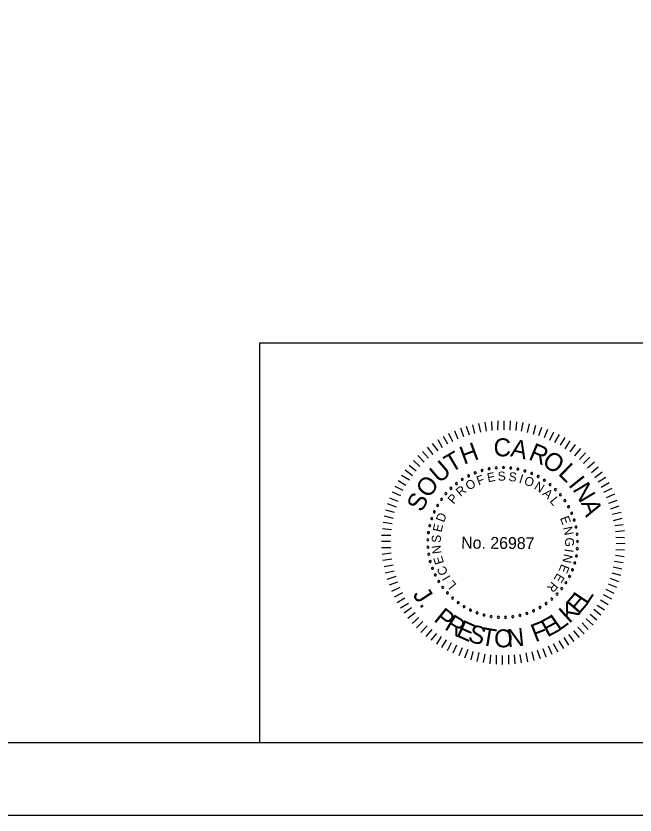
# Model space of a CAD drawing. Extents: x -125.5 to -89.4, y -5.1 to 16.9.
# Drawn here: x -104.58 to -100.31, y -5.07 to 0.43 of the extents above; entities that cross this region are included whole.
import ezdxf

# ---------------------------------------------------------------- set-up
doc = ezdxf.new("R2010")
doc.units = 0
for name, color, linetype in [('BR_BORDER LINES', 7, 'Continuous'), ('BR_TEXT', 7, 'Continuous'), ('Level 31', 7, 'Continuous')]:
    doc.layers.add(name, color=color, linetype=linetype)

msp = doc.modelspace()

# ---------------------------------------------------------------- linework, layer by layer
at = {"layer": 'BR_BORDER LINES'}
for p, q in [((-102.8989, -1.8161), (-97.5337, -1.8161)), ((-102.8989, -4.5661), (-102.8989, -1.8161)), ((-123.6994, -4.5662), (-90.0334, -4.5662))]:
    msp.add_line(p, q, dxfattribs=at)
at = {"layer": 'BR_TEXT'}
for p, q in [((-101.3372, -2.423), (-101.3461, -2.362)), ((-101.2977, -2.419), (-101.3015, -2.3581)), ((-101.2582, -2.4168), (-101.2576, -2.3524)), ((-101.2161, -2.4146), (-101.2156, -2.3528)), ((-101.1741, -2.4175), (-101.1718, -2.3531)), ((-101.1338, -2.4204), (-101.129, -2.3595)), ((-101.0952, -2.425), (-101.0844, -2.3642)), ((-101.4937, -2.4629), (-101.5147, -2.4044)), ((-101.4541, -2.4504), (-101.476, -2.3927)), ((-101.418, -2.4404), (-101.4312, -2.3793)), ((-101.3767, -2.4304), (-101.3908, -2.3711)), ((-101.0549, -2.4331), (-101.0407, -2.374)), ((-101.0138, -2.4437), (-100.9979, -2.3829)), ((-100.977, -2.4543), (-100.9551, -2.397)), ((-100.9376, -2.4675), (-100.9157, -2.4093)), ((-101.604, -2.5144), (-101.6344, -2.46)), ((-101.5695, -2.4966), (-101.5957, -2.4406)), ((-101.5325, -2.4798), (-101.556, -2.4238)), ((-100.9017, -2.485), (-100.8738, -2.4294)), ((-100.8658, -2.5024), (-100.8345, -2.4469)), ((-100.8282, -2.5208), (-100.796, -2.467)), ((-101.6704, -2.5593), (-101.7095, -2.5083)), ((-101.6394, -2.5381), (-101.6698, -2.4838)), ((-100.795, -2.5451), (-100.761, -2.4913)), ((-100.7617, -2.5668), (-100.7252, -2.5165)), ((-101.7369, -2.6094), (-101.7786, -2.5644)), ((-101.7041, -2.5847), (-101.744, -2.5346)), ((-100.7293, -2.5928), (-100.6886, -2.5434)), ((-100.6977, -2.618), (-100.6545, -2.5737)), ((-101.7958, -2.6673), (-101.8392, -2.6248)), ((-101.7663, -2.6366), (-101.8106, -2.5925)), ((-100.6697, -2.6456), (-100.6264, -2.6022)), ((-100.6416, -2.6768), (-100.594, -2.6351)), ((-101.8469, -2.732), (-101.8964, -2.6922)), ((-101.8209, -2.6988), (-101.8704, -2.6598)), ((-100.6144, -2.7088), (-100.5677, -2.6705)), ((-101.8686, -2.761), (-101.9224, -2.728)), ((-100.5906, -2.7424), (-100.5414, -2.7033)), ((-100.5686, -2.7718), (-100.516, -2.7396)), ((-101.9104, -2.8319), (-101.9668, -2.804)), ((-101.893, -2.7977), (-101.9467, -2.7656)), ((-100.5466, -2.8089), (-100.4931, -2.7776)), ((-101.9279, -2.8687), (-101.9852, -2.8433)), ((-100.5288, -2.8433), (-100.4711, -2.8164)), ((-100.5111, -2.8804), (-100.4543, -2.856)), ((-101.9454, -2.9072), (-102.0035, -2.8852)), ((-100.4943, -2.9192), (-100.4374, -2.8982)), ((-101.97, -2.9833), (-102.0308, -2.9682)), ((-101.9577, -2.9474), (-102.0193, -2.9246)), ((-100.4809, -2.9596), (-100.4232, -2.9378)), ((-101.9772, -3.0253), (-102.0397, -3.0094)), ((-100.4708, -2.9957), (-100.4107, -2.9816)), ((-100.4626, -3.0378), (-100.4024, -3.0229)), ((-101.9878, -3.0613), (-102.0487, -3.0531)), ((-100.4543, -3.074), (-100.3951, -3.0667)), ((-101.9925, -3.1024), (-102.0542, -3.0951)), ((-100.4478, -3.1152), (-100.3868, -3.1088)), ((-101.9974, -3.183), (-102.06, -3.1825)), ((-101.9954, -3.1419), (-102.0597, -3.1414)), ((-100.4464, -3.1547), (-100.3863, -3.1552)), ((-101.9961, -3.226), (-102.0604, -3.2272)), ((-100.4471, -3.2388), (-100.3871, -3.241)), ((-100.4442, -3.1959), (-100.3833, -3.1964)), ((-101.9938, -3.2646), (-102.0556, -3.2718)), ((-100.4492, -3.2774), (-100.3883, -3.2856)), ((-101.9898, -3.3058), (-102.0509, -3.3148)), ((-101.9799, -3.3454), (-102.0426, -3.3586)), ((-100.4564, -3.3185), (-100.3972, -3.3284)), ((-101.9733, -3.3875), (-102.0344, -3.4016)), ((-100.4742, -3.3999), (-100.4143, -3.415)), ((-100.4653, -3.3579), (-100.4053, -3.3721)), ((-101.9616, -3.4245), (-102.0236, -3.4454)), ((-101.95, -3.4632), (-102.0085, -3.4842)), ((-100.4848, -3.4367), (-100.4275, -3.4586)), ((-101.9331, -3.5003), (-101.9908, -3.5272)), ((-100.5163, -3.512), (-100.4599, -3.5399)), ((-100.4989, -3.4752), (-100.4424, -3.4971)), ((-101.9162, -3.5364), (-101.9731, -3.566)), ((-101.8994, -3.5735), (-101.9537, -3.6048)), ((-100.5346, -3.5479), (-100.4774, -3.5784)), ((-101.8756, -3.6106), (-101.93, -3.6419)), ((-100.5756, -3.6213), (-100.5235, -3.6535)), ((-100.553, -3.5846), (-100.5, -3.6168)), ((-101.8544, -3.6399), (-101.9045, -3.6764)), ((-101.829, -3.6736), (-101.8791, -3.7127)), ((-100.6224, -3.6836), (-100.5764, -3.7234)), ((-100.5981, -3.6503), (-100.5495, -3.6876)), ((-101.8043, -3.7073), (-101.8485, -3.7481)), ((-101.7754, -3.7333), (-101.8204, -3.7784)), ((-100.6502, -3.7168), (-100.6033, -3.7584)), ((-101.7465, -3.7636), (-101.7889, -3.8095)), ((-101.714, -3.7895), (-101.7548, -3.8364)), ((-100.7073, -3.7721), (-100.6648, -3.8188)), ((-100.6787, -3.7423), (-100.6362, -3.7882)), ((-101.6808, -3.8156), (-101.7207, -3.8633)), ((-101.6501, -3.8373), (-101.6814, -3.8894)), ((-100.8057, -3.8443), (-100.7727, -3.8969)), ((-100.772, -3.8231), (-100.7364, -3.8714)), ((-100.7392, -3.7976), (-100.6993, -3.8452)), ((-101.6151, -3.8599), (-101.6464, -3.9137)), ((-101.5809, -3.8799), (-101.608, -3.9355)), ((-101.5442, -3.8974), (-101.5687, -3.953)), ((-100.9135, -3.9026), (-100.8865, -3.9586)), ((-100.8773, -3.8857), (-100.8468, -3.9418)), ((-100.8393, -3.8663), (-100.808, -3.9206)), ((-101.5057, -3.9149), (-101.5276, -3.9713)), ((-101.4663, -3.9272), (-101.4891, -3.9854)), ((-101.4304, -3.9395), (-101.4446, -3.9986)), ((-101.3892, -3.9467), (-101.4044, -4.0084)), ((-101.3499, -3.9582), (-101.3598, -4.0165)), ((-101.0675, -3.9494), (-101.0542, -4.0113)), ((-101.0262, -3.9429), (-101.0112, -4.0022)), ((-100.9892, -3.9311), (-100.9682, -3.9897)), ((-100.9496, -3.9194), (-100.9286, -3.9763)), ((-101.3104, -3.9628), (-101.3152, -4.0246)), ((-101.271, -3.9657), (-101.2715, -4.0275)), ((-101.229, -3.9686), (-101.2295, -4.0296)), ((-101.1869, -3.9664), (-101.1857, -4.0282)), ((-101.1466, -3.9642), (-101.1428, -4.026)), ((-101.1079, -3.9602), (-101.098, -4.0186))]:
    msp.add_line(p, q, dxfattribs=at)
for centre, start, end in [((-101.3681, -2.6945), 16.1422, 196.1422), ((-101.3681, -2.6945), 196.1422, 16.1422), ((-101.3196, -2.6831), 10.6038, 190.6038), ((-101.3196, -2.6831), 190.6038, 10.6038), ((-101.2702, -2.6764), 5.0653, 185.0653), ((-101.2702, -2.6764), 185.0653, 5.0653), ((-101.2204, -2.6745), 359.5268, 179.5268), ((-101.2204, -2.6745), 179.5268, 359.5268), ((-101.1707, -2.6774), 173.9884, 353.9884), ((-101.1707, -2.6774), 353.9884, 173.9884), ((-101.1214, -2.6851), 168.4499, 348.4499), ((-101.1214, -2.6851), 348.4499, 168.4499), ((-101.0732, -2.6976), 342.9114, 162.9114), ((-101.5039, -2.7559), 32.7576, 212.7576), ((-101.4607, -2.7311), 27.2191, 207.2191), ((-101.4607, -2.7311), 207.2191, 27.2191), ((-101.4153, -2.7106), 21.6807, 201.6807), ((-101.4153, -2.7106), 201.6807, 21.6807), ((-101.0732, -2.6976), 162.9114, 342.9114), ((-101.0263, -2.7146), 157.373, 337.373), ((-101.0263, -2.7146), 337.373, 157.373), ((-100.9814, -2.736), 151.8345, 331.8345), ((-100.9814, -2.736), 331.8345, 151.8345), ((-101.5445, -2.7848), 38.2961, 218.2961), ((-101.5445, -2.7848), 218.2961, 38.2961), ((-101.5039, -2.7559), 212.7576, 32.7576), ((-100.9387, -2.7617), 146.2961, 326.2961), ((-100.9387, -2.7617), 326.2961, 146.2961), ((-100.8987, -2.7914), 140.7576, 320.7576), ((-100.8987, -2.7914), 320.7576, 140.7576), ((-101.6164, -2.8536), 49.373, 229.373), ((-101.6164, -2.8536), 229.373, 49.373), ((-101.5821, -2.8175), 43.8345, 223.8345), ((-101.5821, -2.8175), 223.8345, 43.8345), ((-100.8617, -2.8249), 135.2191, 315.2191), ((-100.8617, -2.8249), 315.2191, 135.2191), ((-100.8282, -2.8617), 129.6807, 309.6807), ((-100.8282, -2.8617), 309.6807, 129.6807), ((-101.6471, -2.8929), 54.9114, 234.9114), ((-101.6471, -2.8929), 234.9114, 54.9114), ((-100.7983, -2.9016), 124.1422, 304.1422), ((-100.7983, -2.9016), 304.1422, 124.1422), ((-101.6738, -2.935), 60.4499, 240.4499), ((-101.6738, -2.935), 240.4499, 60.4499), ((-100.7724, -2.9442), 118.6038, 298.6038), ((-100.7724, -2.9442), 298.6038, 118.6038), ((-101.7145, -3.0258), 71.5268, 251.5268), ((-101.7145, -3.0258), 251.5268, 71.5268), ((-101.6964, -2.9794), 65.9884, 245.9884), ((-101.6964, -2.9794), 245.9884, 65.9884), ((-100.7508, -2.9891), 113.0653, 293.0653), ((-100.7508, -2.9891), 293.0653, 113.0653), ((-101.7281, -3.0738), 77.0653, 257.0653), ((-101.7281, -3.0738), 257.0653, 77.0653), ((-100.7336, -3.0359), 107.5268, 287.5268), ((-100.7336, -3.0359), 287.5268, 107.5268), ((-100.721, -3.0841), 101.9884, 281.9884), ((-100.721, -3.0841), 281.9884, 101.9884), ((-101.737, -3.1228), 82.6038, 262.6038), ((-101.737, -3.1228), 262.6038, 82.6038), ((-100.7131, -3.1333), 96.4499, 276.4499), ((-100.7131, -3.1333), 276.4499, 96.4499), ((-101.7411, -3.1724), 88.1422, 268.1422), ((-101.7411, -3.1724), 268.1422, 88.1422), ((-100.71, -3.183), 90.9114, 270.9114), ((-100.71, -3.183), 270.9114, 90.9114), ((-101.7404, -3.2223), 93.6807, 273.6807), ((-101.7404, -3.2223), 273.6807, 93.6807), ((-100.7118, -3.2328), 85.373, 265.373), ((-100.7118, -3.2328), 265.373, 85.373), ((-101.7349, -3.2718), 99.2191, 279.2191), ((-101.7349, -3.2718), 279.2191, 99.2191), ((-100.7183, -3.2822), 79.8345, 259.8345), ((-100.7183, -3.2822), 259.8345, 79.8345), ((-101.7246, -3.3206), 104.7576, 284.7576), ((-101.7246, -3.3206), 284.7576, 104.7576), ((-100.7295, -3.3308), 74.2961, 254.2961), ((-100.7295, -3.3308), 254.2961, 74.2961), ((-101.7097, -3.3681), 110.2961, 290.2961), ((-101.7097, -3.3681), 290.2961, 110.2961), ((-101.6903, -3.414), 115.8345, 295.8345), ((-101.6903, -3.414), 295.8345, 115.8345), ((-100.7454, -3.378), 68.7576, 248.7576), ((-100.7454, -3.378), 248.7576, 68.7576), ((-101.6665, -3.4578), 121.373, 301.373), ((-101.6665, -3.4578), 301.373, 121.373), ((-100.7904, -3.4668), 57.6807, 237.6807), ((-100.7904, -3.4668), 237.6807, 57.6807), ((-100.7658, -3.4235), 63.2191, 243.2191), ((-100.7658, -3.4235), 243.2191, 63.2191), ((-101.6386, -3.4991), 126.9114, 306.9114), ((-101.6386, -3.4991), 306.9114, 126.9114), ((-100.8192, -3.5075), 52.1422, 232.1422), ((-100.8192, -3.5075), 232.1422, 52.1422), ((-101.6069, -3.5375), 132.4499, 312.4499), ((-101.6069, -3.5375), 312.4499, 132.4499), ((-101.5716, -3.5727), 137.9884, 317.9884), ((-101.5716, -3.5727), 317.9884, 137.9884), ((-100.8877, -3.5797), 41.0653, 221.0653), ((-100.8517, -3.5452), 46.6038, 226.6038), ((-100.8517, -3.5452), 226.6038, 46.6038), ((-101.5331, -3.6043), 143.5268, 323.5268), ((-101.5331, -3.6043), 323.5268, 143.5268), ((-101.4917, -3.632), 149.0653, 329.0653), ((-101.4917, -3.632), 329.0653, 149.0653), ((-100.9269, -3.6105), 35.5268, 215.5268), ((-100.9269, -3.6105), 215.5268, 35.5268), ((-100.8877, -3.5797), 221.0653, 41.0653), ((-101.4478, -3.6556), 154.6038, 334.6038), ((-101.4478, -3.6556), 334.6038, 154.6038), ((-101.4018, -3.6749), 160.1422, 340.1422), ((-101.4018, -3.6749), 340.1422, 160.1422), ((-101.3542, -3.6896), 345.6807, 165.6807), ((-101.0595, -3.6784), 18.9114, 198.9114), ((-101.0595, -3.6784), 198.9114, 18.9114), ((-101.0132, -3.6601), 24.4499, 204.4499), ((-101.0132, -3.6601), 204.4499, 24.4499), ((-100.9688, -3.6374), 29.9884, 209.9884), ((-100.9688, -3.6374), 209.9884, 29.9884), ((-101.3542, -3.6896), 165.6807, 345.6807), ((-101.3054, -3.6997), 351.2191, 171.2191), ((-101.3054, -3.6997), 171.2191, 351.2191), ((-101.2559, -3.705), 356.7576, 176.7576), ((-101.2559, -3.705), 176.7576, 356.7576), ((-101.2061, -3.7055), 2.2961, 182.2961), ((-101.2061, -3.7055), 182.2961, 2.2961), ((-101.1564, -3.7012), 7.8345, 187.8345), ((-101.1564, -3.7012), 187.8345, 7.8345), ((-101.1074, -3.6921), 13.373, 193.373), ((-101.1074, -3.6921), 193.373, 13.373)]:
    msp.add_arc(centre, 0.00701, start, end, dxfattribs=at)
at = {"layer": 'Level 31'}
msp.add_lwpolyline([(-125.5328, -5.0661), (-89.5328, -5.0661), (-89.5328, 16.9339), (-125.5328, 16.9339)], close=True, dxfattribs=at)

# ---------------------------------------------------------------- texts
at = {"layer": 'BR_TEXT'}
for s, height, rotation, p in [('C', 0.1241, 359.5482, (-101.2889, -2.5969)), ('H', 0.1241, 20.3637, (-101.4933, -2.6552)), ('A', 0.1241, 348.1981, (-101.1775, -2.5961)), ('R', 0.1241, 337.4344, (-101.0542, -2.616)), ('T', 0.1241, 30.4992, (-101.5812, -2.7128)), ('O', 0.1239, 326.5869, (-100.962, -2.6528)), ('U', 0.1241, 40.8022, (-101.6624, -2.7875)), ('L', 0.1241, 315.9488, (-100.8494, -2.7205)), ('O', 0.1241, 52.0267, (-101.7369, -2.8914)), ('F', 0.0622, 20.6127, (-101.392, -2.7981)), ('E', 0.0622, 11.4103, (-101.3269, -2.7764)), ('S', 0.0622, 2.208, (-101.2591, -2.7654)), ('S', 0.0622, 352.6608, (-101.1878, -2.7657)), ('I', 0.0622, 343.1136, (-101.1175, -2.7777)), ('O', 0.0622, 338.4392, (-101.0841, -2.7878)), ('I', 0.1241, 308.6613, (-100.778, -2.7948)), ('R', 0.0622, 40.3949, (-101.5156, -2.878)), ('O', 0.0622, 30.8477, (-101.4594, -2.8341)), ('N', 0.0622, 328.2042, (-101.0145, -2.8192)), ('N', 0.1241, 300.7037, (-100.7474, -2.8242)), ('S', 0.1239, 63.2511, (-101.7823, -2.9871)), ('P', 0.0622, 49.9421, (-101.5636, -2.9306)), ('A', 0.0622, 318.657, (-100.9555, -2.8592)), ('L', 0.0622, 309.4546, (-100.9057, -2.9066)), ('A', 0.1241, 289.4792, (-100.6882, -2.9172)), ('D', 0.0622, 69.0364, (-101.6306, -3.0559)), ('E', 0.0622, 291.049, (-100.8319, -3.0219)), ('E', 0.0622, 78.2388, (-101.6472, -3.1226)), ('N', 0.0622, 281.8466, (-100.8097, -3.0869)), ('S', 0.0622, 87.786, (-101.6529, -3.1936)), ('No. 26987', 0.08175, 359.5268, (-101.5118, -3.232)), ('G', 0.0622, 272.2995, (-100.7979, -3.1572)), ('N', 0.0622, 97.3332, (-101.6467, -3.2646)), ('I', 0.0622, 262.4084, (-100.7983, -3.231)), ('E', 0.0622, 106.5355, (-101.6297, -3.3312)), ('N', 0.0622, 257.7339, (-100.8028, -3.2656)), ('C', 0.0622, 116.4266, (-101.5998, -3.3987)), ('E', 0.0622, 248.1867, (-100.8209, -3.3346)), ('E', 0.0622, 238.9844, (-100.8488, -3.3973)), ('I', 0.0622, 121.1011, (-101.5818, -3.4285)), ('L', 0.0622, 129.9595, (-101.5411, -3.4807)), ('R', 0.0622, 229.782, (-100.8865, -3.4548)), ('J', 0.1236, 302.9559, (-101.849, -3.5492)), ('E', 0.1236, 49.3639, (-100.703, -3.6911)), ('L', 0.1236, 56.4247, (-100.6455, -3.6233)), ('.', 0.1236, 309.3974, (-101.8049, -3.6172)), ('K', 0.1236, 42.3031, (-100.7683, -3.7512)), ('P', 0.1236, 321.1035, (-101.7065, -3.7264)), ('R', 0.1236, 328.5359, (-101.6332, -3.7844)), ('E', 0.1236, 335.9684, (-101.5531, -3.8325)), ('F', 0.1236, 21.1206, (-101.0013, -3.8776)), ('E', 0.1236, 28.1814, (-100.9186, -3.8452)), ('L', 0.1236, 35.2422, (-100.8406, -3.8028)), ('S', 0.1236, 343.0292, (-101.4718, -3.8682)), ('T', 0.1236, 350.4617, (-101.3821, -3.8947)), ('O', 0.1236, 358.1419, (-101.2867, -3.9097)), ('N', 0.1236, 5.8221, (-101.1902, -3.9118))]:
    msp.add_text(s, height=height, rotation=rotation, dxfattribs=at).set_placement(p)

doc.saveas('drawing.dxf')
